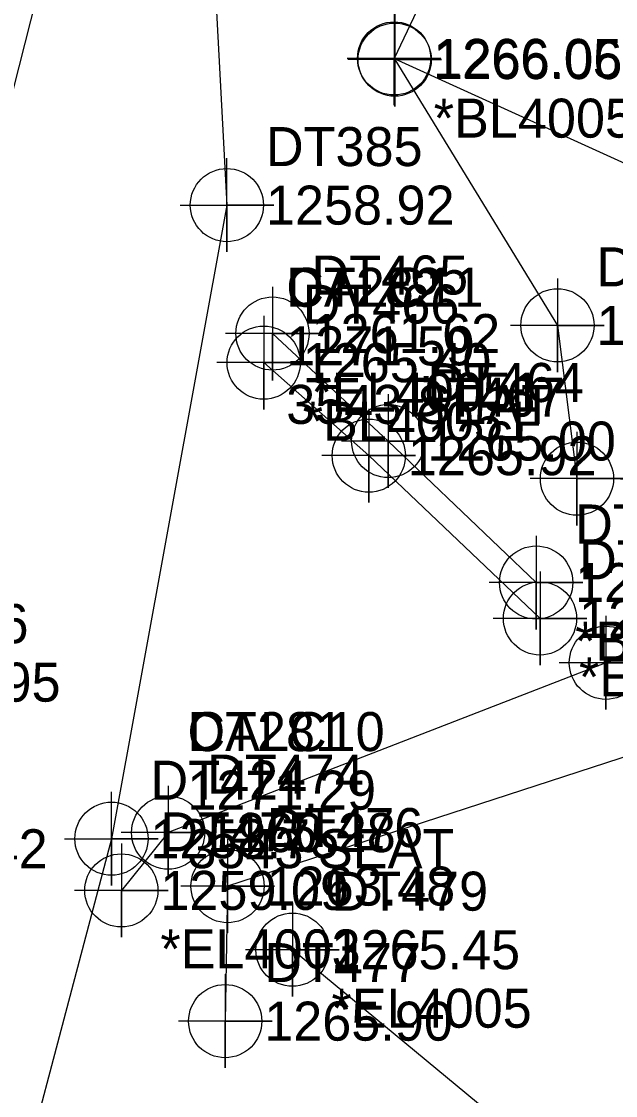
# Model space of a CAD drawing. Extents: x 1391270 to 1392151, y 960049 to 960667.
# Drawn here: x 1391612.7 to 1391650.7, y 960303.3 to 960372.1 of the extents above; entities that cross this region are included whole.
import ezdxf

# ---------------------------------------------------------------- set-up
doc = ezdxf.new("R2010")
doc.units = 0
for name, color, linetype in [('COGO Default Point Elevation', 7, 'Continuous'), ('COGO Default Point Number', 7, 'Continuous'), ('Exist DTM Breakline', 7, 'Continuous'), ('Exist DTM Breakline Cogo Comment', 7, 'Continuous'), ('Exist DTM Breakline Cogo Elevation', 7, 'Continuous'), ('Exist DTM Breakline Cogo Number', 7, 'Continuous'), ('Exist DTM Breakline Cogo Point CELL', 7, 'Continuous'), ('Exist DTM Breakline Underwater', 7, 'Continuous'), ('Exist DTM Breakline Underwater Cogo Elevation', 7, 'Continuous'), ('Exist DTM Drainline', 7, 'Continuous'), ('Exist DTM Drainline Cogo Comment', 7, 'Continuous'), ('Exist DTM Drainline Cogo Elevation', 7, 'Continuous'), ('Exist DTM Drainline Cogo Number', 7, 'Continuous'), ('Exist DTM Drainline Cogo Point CELL', 7, 'Continuous'), ('Exist Hydro Stream or Body of Water', 7, 'Continuous'), ('Exist Hydro Stream or Body of Water Cogo Elevation', 7, 'Continuous'), ('Exist Hydro Stream or Body of Water Cogo Number', 7, 'Continuous'), ('Exist Hydro Stream or Body of Water Cogo Point CELL', 7, 'Continuous'), ('Exist Utilities Power UG Cable Cogo Elevation', 7, 'Continuous'), ('Exist Utilities Power UG Cable Cogo Number', 7, 'Continuous'), ('Exist Utilities Sanitary Sewer Manhole Cogo Comment', 7, 'Continuous'), ('Exist Utilities Sanitary Sewer Manhole Cogo Elevation', 7, 'Continuous'), ('Exist Utilities Sanitary Sewer Manhole Cogo Number', 7, 'Continuous')]:
    doc.layers.add(name, color=color, linetype=linetype)

msp = doc.modelspace()

# ---------------------------------------------------------------- linework, layer by layer
at = {"layer": 'Exist DTM Breakline'}
for p, q in [((1391650.447, 960398.915), (1391636.562, 960369.763)), ((1391636.562, 960369.763), (1391657.996, 960360)), ((1391651.972, 960294.504), (1391630.048, 960312.663))]:
    msp.add_line(p, q, dxfattribs=at)
for points in [[(1391636.599, 960369.686), (1391647.025, 960352.66), (1391648.273, 960342.839), (1391653.852, 960342.804)], [(1391645.66, 960336.185), (1391636.182, 960345.249), (1391628.769, 960352.135)], [(1391628.205, 960350.271), (1391634.939, 960344.313), (1391645.907, 960333.885)], [(1391654.634, 960326.082), (1391625.89, 960316.735), (1391625.74, 960308.084)]]:
    msp.add_lwpolyline(points, dxfattribs=at)
at = {"layer": 'Exist DTM Breakline Cogo Point CELL'}
for points in [[(1391636.562, 960372.763), (1391636.562, 960366.763), (1391636.562, 960369.763), (1391639.562, 960369.763), (1391633.562, 960369.763)], [(1391636.599, 960372.686), (1391636.599, 960366.686), (1391636.599, 960369.686), (1391639.599, 960369.686), (1391633.599, 960369.686)], [(1391628.769, 960355.135), (1391628.769, 960349.135), (1391628.769, 960352.135), (1391631.769, 960352.135), (1391625.769, 960352.135)], [(1391647.025, 960355.66), (1391647.025, 960349.66), (1391647.025, 960352.66), (1391650.025, 960352.66), (1391644.025, 960352.66)], [(1391628.205, 960353.271), (1391628.205, 960347.271), (1391628.205, 960350.271), (1391631.205, 960350.271), (1391625.205, 960350.271)], [(1391636.182, 960348.249), (1391636.182, 960342.249), (1391636.182, 960345.249), (1391639.182, 960345.249), (1391633.182, 960345.249)], [(1391634.939, 960347.313), (1391634.939, 960341.313), (1391634.939, 960344.313), (1391637.939, 960344.313), (1391631.939, 960344.313)], [(1391648.273, 960345.839), (1391648.273, 960339.839), (1391648.273, 960342.839), (1391651.273, 960342.839), (1391645.273, 960342.839)], [(1391645.66, 960339.185), (1391645.66, 960333.185), (1391645.66, 960336.185), (1391648.66, 960336.185), (1391642.66, 960336.185)], [(1391645.907, 960336.885), (1391645.907, 960330.885), (1391645.907, 960333.885), (1391648.907, 960333.885), (1391642.907, 960333.885)], [(1391625.89, 960319.735), (1391625.89, 960313.735), (1391625.89, 960316.735), (1391628.89, 960316.735), (1391622.89, 960316.735)], [(1391630.048, 960315.663), (1391630.048, 960309.663), (1391630.048, 960312.663), (1391633.048, 960312.663), (1391627.048, 960312.663)], [(1391625.74, 960311.084), (1391625.74, 960305.084), (1391625.74, 960308.084), (1391628.74, 960308.084), (1391622.74, 960308.084)]]:
    msp.add_lwpolyline(points, dxfattribs=at)
for centre in [(1391636.562, 960369.763), (1391636.599, 960369.686), (1391628.769, 960352.135), (1391647.025, 960352.66), (1391628.205, 960350.271), (1391636.182, 960345.249), (1391634.939, 960344.313), (1391648.273, 960342.839), (1391645.66, 960336.185), (1391645.907, 960333.885), (1391625.89, 960316.735), (1391630.048, 960312.663), (1391625.74, 960308.084)]:
    msp.add_circle(centre, 2.344, dxfattribs=at)
at = {"layer": 'Exist DTM Breakline Underwater'}
msp.add_lwpolyline([(1391637.721, 960501.208), (1391621.569, 960466.64), (1391617.066, 960434.832), (1391615.14, 960379.594), (1391599.785, 960319.127), (1391597.418, 960292.355)], dxfattribs=at)
at = {"layer": 'Exist DTM Drainline'}
msp.add_lwpolyline([(1391681.358, 960310.71), (1391671.053, 960321.651), (1391663.547, 960327.701), (1391659.373, 960333.698), (1391650.127, 960331.045), (1391622.084, 960320.163), (1391619.087, 960316.46)], dxfattribs=at)
at = {"layer": 'Exist DTM Drainline Cogo Point CELL'}
for points in [[(1391650.127, 960334.045), (1391650.127, 960328.045), (1391650.127, 960331.045), (1391653.127, 960331.045), (1391647.127, 960331.045)], [(1391622.084, 960323.163), (1391622.084, 960317.163), (1391622.084, 960320.163), (1391625.084, 960320.163), (1391619.084, 960320.163)], [(1391619.087, 960319.46), (1391619.087, 960313.46), (1391619.087, 960316.46), (1391622.087, 960316.46), (1391616.087, 960316.46)]]:
    msp.add_lwpolyline(points, dxfattribs=at)
for centre in [(1391650.127, 960331.045), (1391622.084, 960320.163), (1391619.087, 960316.46)]:
    msp.add_circle(centre, 2.344, dxfattribs=at)
at = {"layer": 'Exist Hydro Stream or Body of Water'}
msp.add_lwpolyline([(1391649.062, 960494.038), (1391648.634, 960466.546), (1391627.196, 960433.7), (1391623.135, 960411.167), (1391625.85, 960360.364), (1391618.453, 960319.772), (1391609.949, 960287.686), (1391599.63, 960231.778)], dxfattribs=at)
at = {"layer": 'Exist Hydro Stream or Body of Water Cogo Point CELL'}
for points in [[(1391622.85, 960360.364), (1391628.85, 960360.364), (1391625.85, 960360.364), (1391625.85, 960357.364), (1391625.85, 960363.364)], [(1391615.453, 960319.772), (1391621.453, 960319.772), (1391618.453, 960319.772), (1391618.453, 960316.772), (1391618.453, 960322.772)]]:
    msp.add_lwpolyline(points, dxfattribs=at)
for centre in [(1391625.85, 960360.364), (1391618.453, 960319.772)]:
    msp.add_circle(centre, 2.344, dxfattribs=at)

# ---------------------------------------------------------------- texts
at = {"layer": 'COGO Default Point Elevation'}
for s, p in [('1271.59', (1391629.648, 960350.098)), ('1271.29', (1391623.319, 960321.634))]:
    msp.add_text(s, height=2.5, dxfattribs=at).set_placement(p)
at = {"layer": 'COGO Default Point Number'}
for s, p in [('CALC11', (1391629.648, 960353.848)), ('CALC10', (1391623.319, 960325.384))]:
    msp.add_text(s, height=2.5, dxfattribs=at).set_placement(p)
at = {"layer": 'Exist DTM Breakline Cogo Comment'}
for s, p in [('*BL40051', (1391639.099, 960364.686)), ('*EL40051', (1391631.269, 960347.135)), ('*BL40051', (1391630.705, 960345.271)), ('*BL40051', (1391648.16, 960331.185)), ('*EL40051', (1391648.407, 960328.885)), ('*EL4005', (1391632.548, 960307.663))]:
    msp.add_text(s, height=2.5, dxfattribs=at).set_placement(p)
at = {"layer": 'Exist DTM Breakline Cogo Elevation'}
for s, p in [('1266.05', (1391639.062, 960368.513)), ('1266.06', (1391639.099, 960368.436)), ('1269.60', (1391649.525, 960351.41)), ('1261.62', (1391631.269, 960350.885)), ('1265.40', (1391630.705, 960349.021)), ('1265.00', (1391638.682, 960343.999)), ('1265.92', (1391637.439, 960343.063)), ('1265.63', (1391648.16, 960334.935)), ('1266.77', (1391648.407, 960332.635)), ('1263.48', (1391628.39, 960315.485)), ('1265.45', (1391632.548, 960311.413)), ('1265.90', (1391628.24, 960306.834))]:
    msp.add_text(s, height=2.5, dxfattribs=at).set_placement(p)
at = {"layer": 'Exist DTM Breakline Cogo Number'}
for s, p in [('DT390', (1391649.525, 960355.16)), ('DT465', (1391631.269, 960354.635)), ('DT466', (1391630.705, 960352.771)), ('DT464', (1391638.682, 960347.749)), ('DT467', (1391637.439, 960346.813)), ('DT463', (1391648.16, 960338.685)), ('DT468', (1391648.407, 960336.385)), ('DT476', (1391628.39, 960319.235)), ('DT479', (1391632.548, 960315.163)), ('DT477', (1391628.24, 960310.584))]:
    msp.add_text(s, height=2.5, dxfattribs=at).set_placement(p)
at = {"layer": 'Exist DTM Breakline Underwater Cogo Elevation'}
msp.add_text('1257.42', height=2.5, dxfattribs=at).set_placement((1391602.285, 960317.877))
at = {"layer": 'Exist DTM Drainline Cogo Comment'}
msp.add_text('*EL4003', height=2.5, dxfattribs=at).set_placement((1391621.587, 960311.46))
at = {"layer": 'Exist DTM Drainline Cogo Elevation'}
for s, p in [('1260.28', (1391624.584, 960318.913)), ('1259.09', (1391621.587, 960315.21))]:
    msp.add_text(s, height=2.5, dxfattribs=at).set_placement(p)
at = {"layer": 'Exist DTM Drainline Cogo Number'}
for s, p in [('DT474', (1391624.584, 960322.663)), ('DT475', (1391621.587, 960318.96))]:
    msp.add_text(s, height=2.5, dxfattribs=at).set_placement(p)
at = {"layer": 'Exist Hydro Stream or Body of Water Cogo Elevation'}
for s, p in [('1258.92', (1391628.35, 960359.114)), ('1258.75', (1391620.953, 960318.522))]:
    msp.add_text(s, height=2.5, dxfattribs=at).set_placement(p)
at = {"layer": 'Exist Hydro Stream or Body of Water Cogo Number'}
for s, p in [('DT385', (1391628.35, 960362.864)), ('DT424', (1391620.953, 960322.272))]:
    msp.add_text(s, height=2.5, dxfattribs=at).set_placement(p)
at = {"layer": 'Exist Utilities Power UG Cable Cogo Elevation'}
msp.add_text('1286.95', height=2.5, dxfattribs=at).set_placement((1391603.109, 960328.553))
at = {"layer": 'Exist Utilities Power UG Cable Cogo Number'}
msp.add_text('DT436', height=2.5, dxfattribs=at).set_placement((1391603.109, 960332.303))
at = {"layer": 'Exist Utilities Sanitary Sewer Manhole Cogo Comment'}
for p in [(1391629.648, 960346.348), (1391623.319, 960317.884)]:
    msp.add_text('3543 SEAT', height=2.5, dxfattribs=at).set_placement(p)
at = {"layer": 'Exist Utilities Sanitary Sewer Manhole Cogo Elevation'}
for s, p in [('1271.59', (1391629.648, 960350.098)), ('1271.29', (1391623.319, 960321.634))]:
    msp.add_text(s, height=2.5, dxfattribs=at).set_placement(p)
at = {"layer": 'Exist Utilities Sanitary Sewer Manhole Cogo Number'}
for s, p in [('DT282', (1391629.648, 960353.848)), ('DT281', (1391623.319, 960325.384))]:
    msp.add_text(s, height=2.5, dxfattribs=at).set_placement(p)

doc.saveas('drawing.dxf')
